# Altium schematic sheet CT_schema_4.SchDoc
size 577 x 363 mm
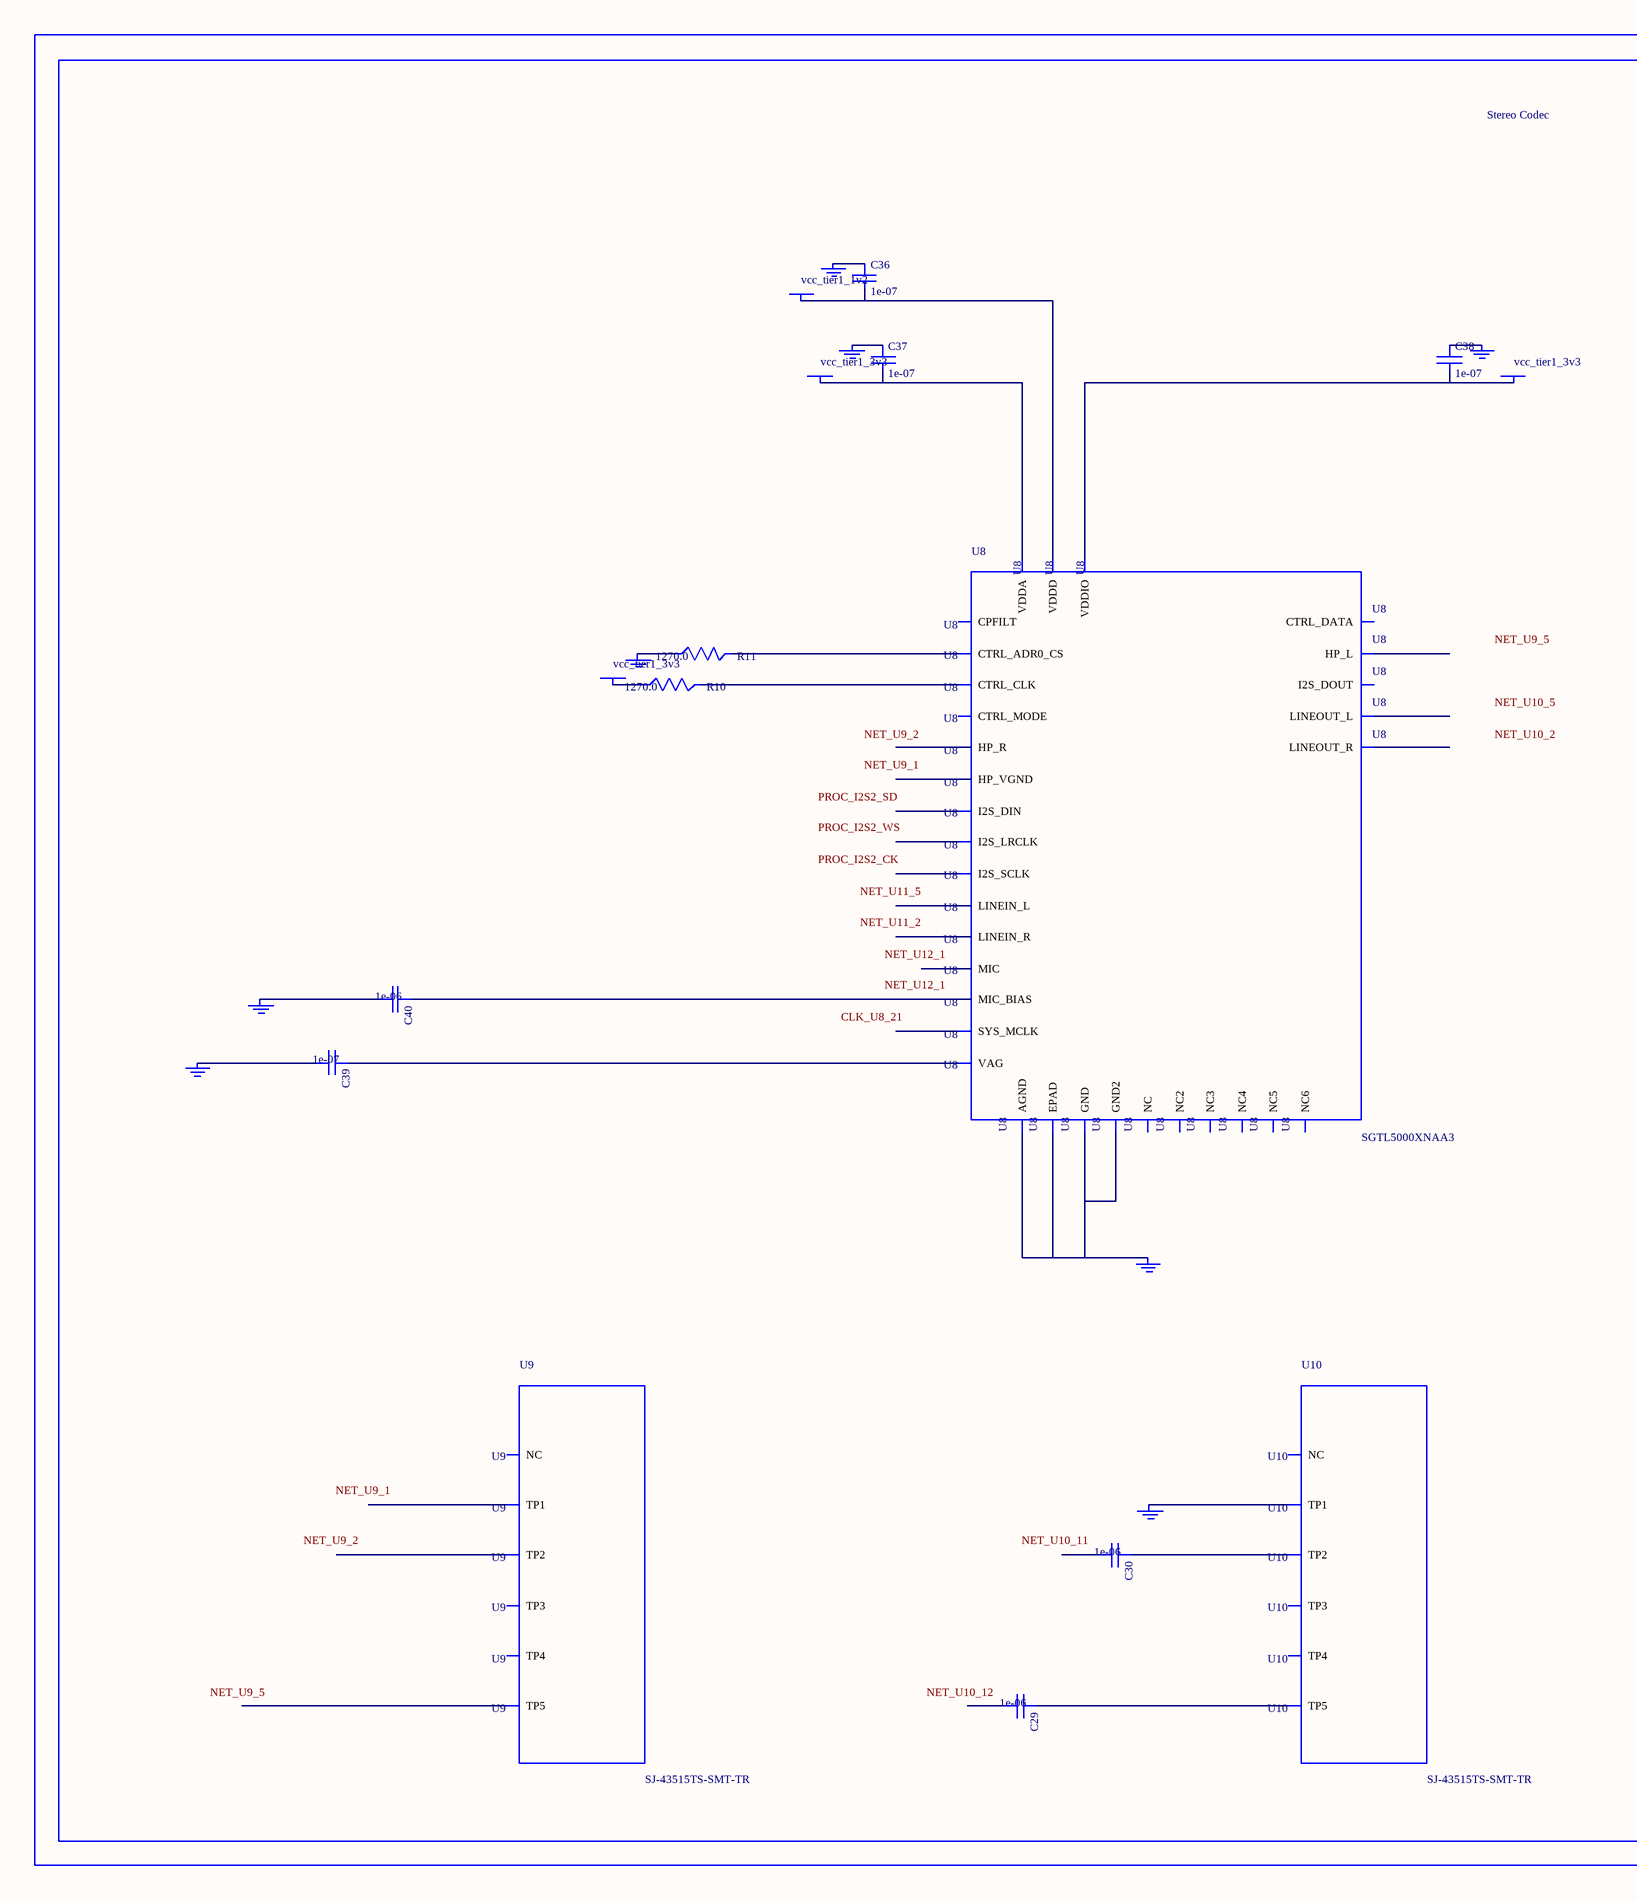
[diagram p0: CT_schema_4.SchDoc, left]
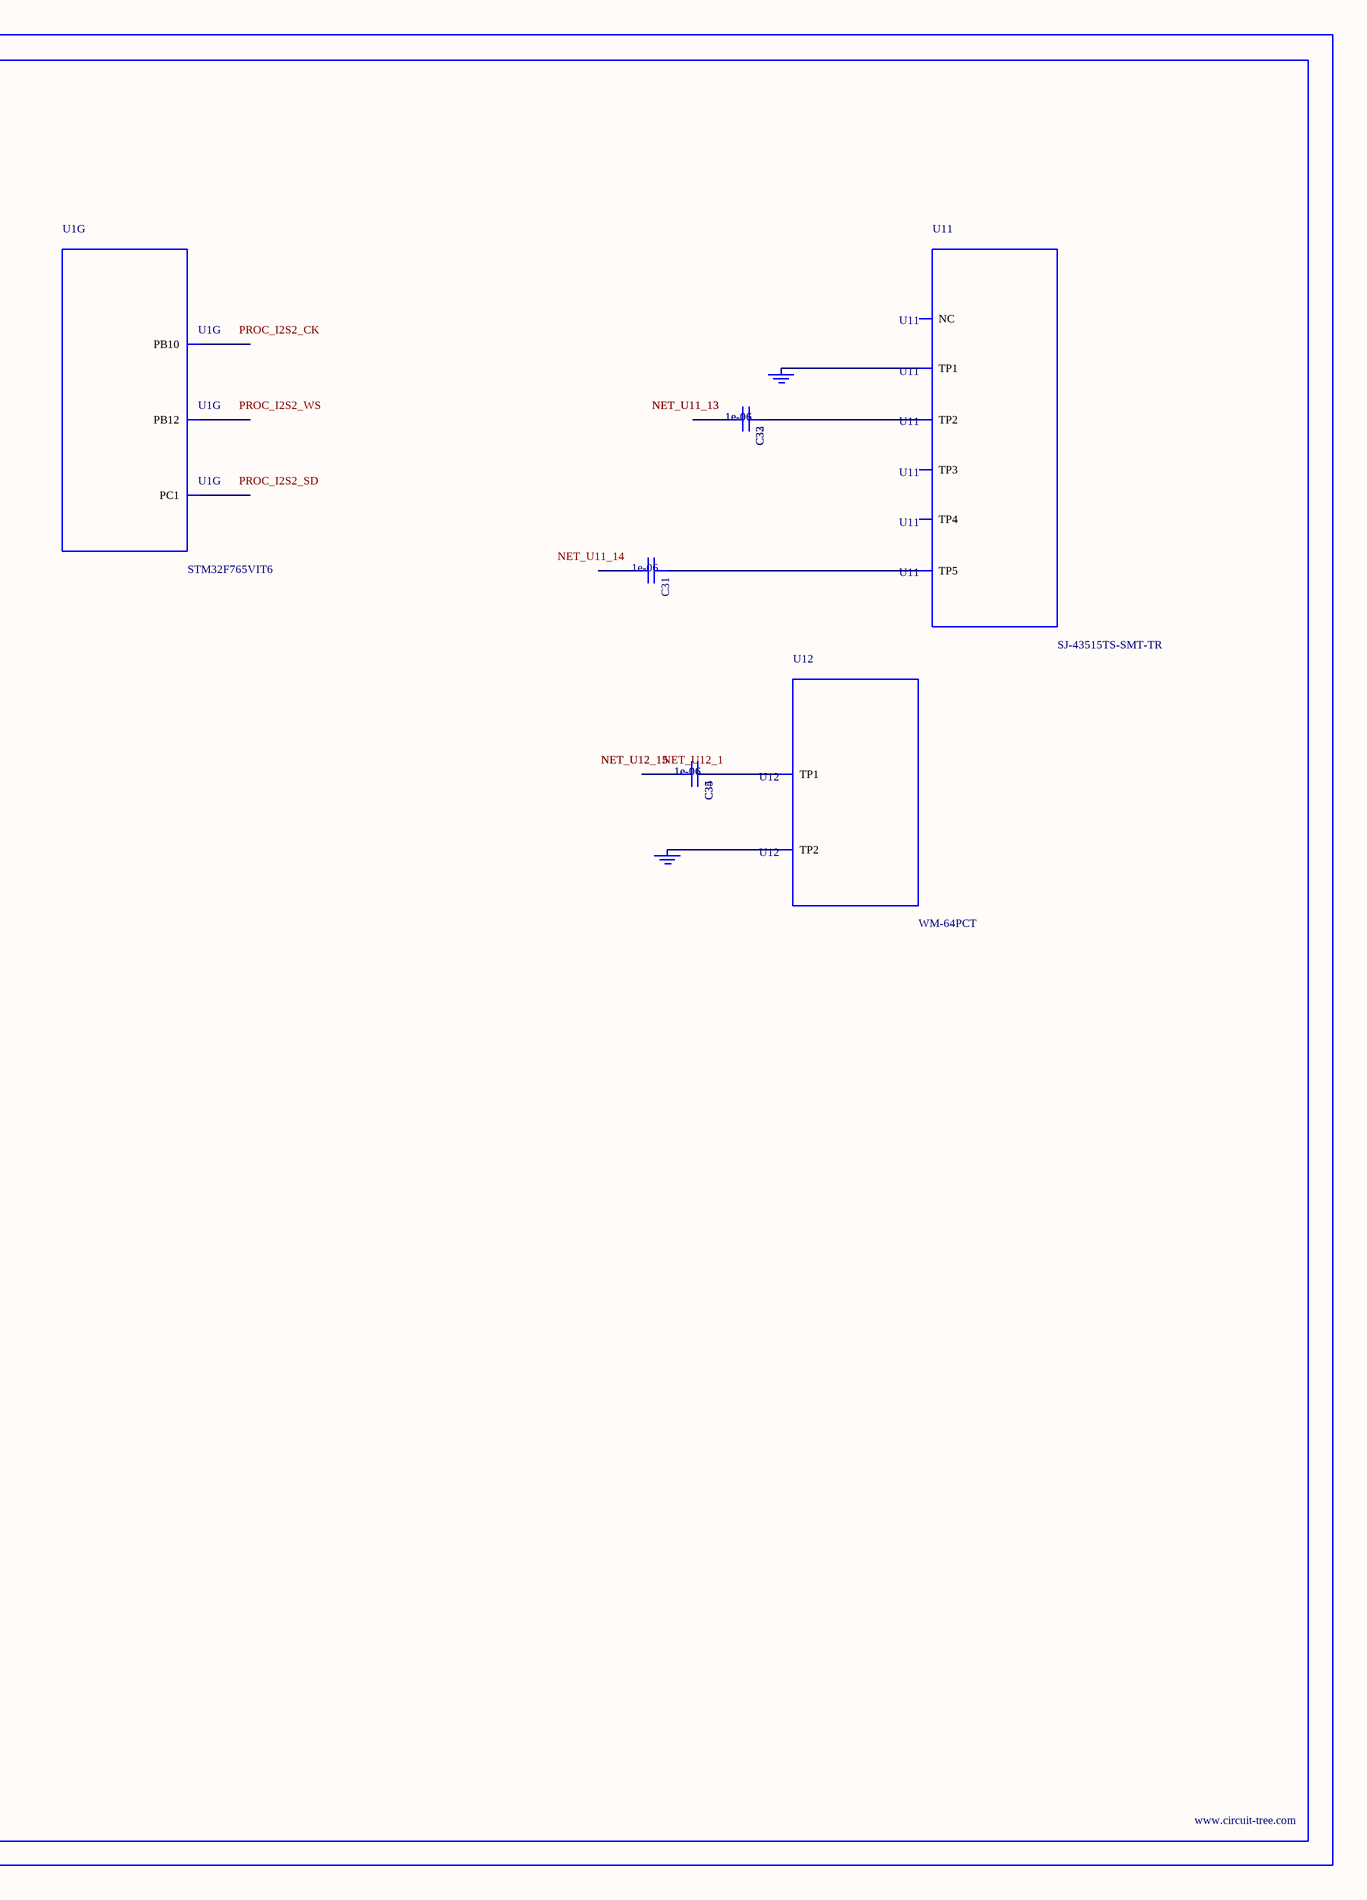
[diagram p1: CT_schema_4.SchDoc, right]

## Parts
BORDER3  (no value)
C29  1e-06  [C0603]
C30  1e-06  [C0603]
C31  1e-06  [C0603]
C32  1e-06  [C0603]
C33  1e-06  [C0603]
C34  1e-06  [C0603]
C35  1e-06  [C0603]
C36  1e-07  [C0402]
C37  1e-07  [C0402]
C38  1e-07  [C0402]
C39  1e-07  [C0402]
C40  1e-06  [C0603]
GND_INSTANCE_3_0  (no value)
GND_INSTANCE_3_1  (no value)
GND_INSTANCE_3_2  (no value)
GND_INSTANCE_3_3  (no value)
GND_INSTANCE_3_4  (no value)
GND_INSTANCE_3_5  (no value)
GND_INSTANCE_3_6  (no value)
GND_INSTANCE_3_7  (no value)
GND_INSTANCE_3_8  (no value)
GND_INSTANCE_3_9  (no value)
GND_INSTANCE_3_10  (no value)
POWER_INSTANCE_3_0  vcc_tier1_3v3
POWER_INSTANCE_3_1  vcc_tier1_3v3
POWER_INSTANCE_3_2  vcc_tier1_3v3
POWER_INSTANCE_3_3  vcc_tier1_1v2
R10  1270.0  [R0603]
R11  1270.0  [R0603]
U1  STM32F765VIT6  [LQFP100]  (part G of 10)
U8  SGTL5000XNAA3  [QFN-32]
U9  SJ-43515TS-SMT-TR  [SJ-43515TS-SMT-TR]
U10  SJ-43515TS-SMT-TR  [SJ-43515TS-SMT-TR]
U11  SJ-43515TS-SMT-TR  [SJ-43515TS-SMT-TR]
U12  WM-64PCT  [WM-64PC]

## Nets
NetC29_1: C29.1 U10.5(TP5)
NetC30_1: C30.1 U10.2(TP2)
NetC31_1: C31.1 U11.5(TP5)
NetC32_1: C32.1 C33.1 U11.2(TP2)
NetC32_2: C32.2 C33.2
NetC34_1: C34.1 C35.1 U12.1(TP1)
NetC34_2: C34.2 C35.2
NetC36_1: C36.1 GND_INSTANCE_3_5.0(GND)
NetC36_2: C36.2 POWER_INSTANCE_3_3.0(PWR) U8.30(VDDD)
NetC37_1: C37.1 GND_INSTANCE_3_1.0(GND)
NetC37_2: C37.2 POWER_INSTANCE_3_0.0(PWR) U8.5(VDDA)
NetC38_1: C38.1 GND_INSTANCE_3_4.0(GND)
NetC38_2: C38.2 POWER_INSTANCE_3_1.0(PWR) U8.20(VDDIO)
NetC39_1: C39.1 U8.10(VAG)
NetC39_2: C39.2 GND_INSTANCE_3_2.0(GND)
NetC40_1: C40.1 U8.16(MIC_BIAS)
NetC40_2: C40.2 GND_INSTANCE_3_3.0(GND)
NetGND_INSTANCE_3_0_0: GND_INSTANCE_3_0.0(GND) U8.1(GND) U8.3(GND2) U8.7(AGND) U8.EXP(EPAD)
NetGND_INSTANCE_3_6_0: GND_INSTANCE_3_6.0(GND) R11.1
NetGND_INSTANCE_3_7_0: GND_INSTANCE_3_7.0(GND) U10.1(TP1)
NetGND_INSTANCE_3_8_0: GND_INSTANCE_3_8.0(GND) GND_INSTANCE_3_9.0(GND) U11.1(TP1)
NetGND_INSTANCE_3_10_0: GND_INSTANCE_3_10.0(GND) U12.2(TP2)
NetPOWER_INSTANCE_3_2_0: POWER_INSTANCE_3_2.0(PWR) R10.1
NetR10_2: R10.2 U8.29(CTRL_CLK)
NetR11_2: R11.2 U8.31(CTRL_ADR0_CS)

Not connected (* = marked no-connect by the designer): C29 2; C30 2; C31 2; U1 16(PC1) 46(PB10) 51(PB12); U8 2(HP_R) 4(HP_VGND) 6(HP_L) 8(NC) 9(NC2) 11(LINEOUT_R) 12(LINEOUT_L) 13(LINEIN_R) 14(LINEIN_L) 15(MIC) 17(NC3) 18(CPFILT) 19(NC4) 21(SYS_MCLK) 22(NC5) 23(I2S_LRCLK) 24(I2S_SCLK) 25(I2S_DOUT) 26(I2S_DIN) 27(CTRL_DATA) 28(NC6) 32(CTRL_MODE); U9 1(TP1) 2(TP2) 3(TP3) 4(TP4) 5(TP5) 6(NC); U10 3(TP3) 4(TP4) 6(NC); U11 3(TP3) 4(TP4) 6(NC)

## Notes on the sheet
- Labels drawn without touching a wire or pin: CLK_U8_21, NET_U9_1, NET_U9_2, NET_U9_5, NET_U10_2, NET_U10_5, NET_U10_11, NET_U10_12, NET_U11_2, NET_U11_5, NET_U11_14, NET_U12_1, PROC_I2S2_CK, PROC_I2S2_SD, PROC_I2S2_WS

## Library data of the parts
BORDER3 = BORDER_PAGE3
C29-C35 C40 = C0603C105K3RACTU
C36-C39 = C0402C104K3RACTU
GND_INSTANCE_3_0-GND_INSTANCE_3_10 = GND
POWER_INSTANCE_3_0-POWER_INSTANCE_3_3 = PWR
R10 R11 = RC0603FR-071K27L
